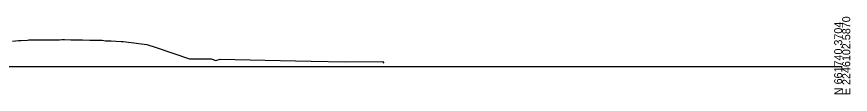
# Model space of a CAD drawing. Extents: x -26 to 603, y -10 to 9526.
# Drawn here: x 311.3 to 602.8, y 1490.3 to 1517.3 of the extents above; entities that cross this region are included whole.
import ezdxf

# ---------------------------------------------------------------- set-up
doc = ezdxf.new("R2010")
doc.units = 0
doc.layers.add('Exist Cross Section Cell', color=7, linetype='Continuous')
doc.layers.add('Exist XS Ground Line', color=7, linetype='Continuous')

msp = doc.modelspace()

# ---------------------------------------------------------------- linework, layer by layer
at = {"layer": 'Exist Cross Section Cell'}
msp.add_line((300, 1500), (600, 1500), dxfattribs=at)
at = {"layer": 'Exist XS Ground Line'}
for p, q in [((309.76, 1508.87), (311.89, 1509.04)), ((311.89, 1509.04), (312.89, 1509.09)), ((312.89, 1509.09), (315, 1509.2)), ((315, 1509.2), (315.55, 1509.27)), ((315.55, 1509.27), (316.01, 1509.27)), ((316.01, 1509.27), (317.65, 1509.26)), ((317.65, 1509.26), (320.33, 1509.27)), ((320.33, 1509.27), (324.2, 1509.31)), ((324.2, 1509.31), (325.82, 1509.32)), ((325.82, 1509.32), (326.21, 1509.33)), ((326.21, 1509.33), (327.02, 1509.38)), ((327.02, 1509.38), (327.97, 1509.35)), ((327.97, 1509.35), (330.21, 1509.3)), ((330.21, 1509.3), (331.31, 1509.28)), ((331.31, 1509.28), (334.26, 1509.23)), ((334.26, 1509.23), (336.81, 1509.19)), ((336.81, 1509.19), (337.37, 1509.18)), ((337.37, 1509.18), (338.39, 1509.16)), ((338.39, 1509.16), (339.16, 1509.16)), ((339.16, 1509.16), (339.61, 1509.13)), ((339.61, 1509.13), (340.17, 1509.12)), ((340.17, 1509.12), (341.16, 1509.11)), ((341.16, 1509.11), (341.69, 1509.04)), ((341.69, 1509.04), (342.3, 1508.97)), ((342.3, 1508.97), (344.32, 1508.89)), ((344.32, 1508.89), (347.79, 1508.76)), ((347.79, 1508.76), (348.53, 1508.68)), ((348.53, 1508.68), (350.37, 1508.46)), ((350.37, 1508.46), (356.73, 1507.66)), ((356.73, 1507.66), (360.06, 1506.59)), ((360.06, 1506.59), (371.66, 1502.69)), ((371.66, 1502.69), (379.29, 1502.61)), ((379.29, 1502.61), (380.96, 1502.07)), ((380.96, 1502.07), (382.46, 1502.58)), ((382.46, 1502.58), (398.2, 1502.21)), ((398.2, 1502.21), (408.84, 1502)), ((408.84, 1502), (414.27, 1501.89)), ((414.27, 1501.89), (426.32, 1501.58)), ((426.32, 1501.58), (439.19, 1501.68)), ((439.19, 1501.68), (439.64, 1501.15))]:
    msp.add_line(p, q, dxfattribs=at)

# ---------------------------------------------------------------- texts
at = {"layer": 'Exist Cross Section Cell'}
for s, p in [('E 2246102.5870', (602.8, 1490)), ('N 661740.3704', (600, 1490))]:
    msp.add_text(s, height=2.8, rotation=90, dxfattribs=at).set_placement(p)

doc.saveas('drawing.dxf')
